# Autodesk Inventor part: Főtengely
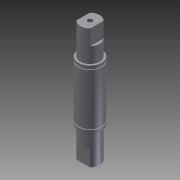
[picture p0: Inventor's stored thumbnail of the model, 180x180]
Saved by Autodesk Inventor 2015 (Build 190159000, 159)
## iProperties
Created: 2013-02
Part Number: Főtengely
Material: Generic
Document SubType Name: Modeling
Designer: Marci
Density: 1 g/cm^3
Appearance: Default
Author: Marci
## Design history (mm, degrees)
sketch "Sketch1"
  geometry: C1 r 15 at (0, 0); 1 further point
  constraints: 1 centre point, 1 coincident
  dimensions: "d0" = 30 diameter of C1
extrude "Extrusion1" new body sketch "Sketch1" distance "d1" = 76; taper "d2" = 0 deg
sketch "Sketch2"
  geometry: C1 r 15 at (0, 0) reference; C2 r 12.5 at (0, 0)
  constraints: 1 centre point, 1 coincident
  dimensions: "d3" = 25 diameter of C2
extrude "Extrusion2" join sketch "Sketch2" distance "d4" = 34; taper "d5" = 0 deg
sketch "Sketch3"
  geometry: C1 r 15 at (0, 0) reference; C2 r 12.5 at (0, 0)
  constraints: 1 centre point, 1 coincident
  dimensions: "d6" = 25 diameter of C2
extrude "Extrusion3" join sketch "Sketch3" distance "d7" = 34; taper "d8" = 0 deg
sketch "Sketch4"
  geometry: L1 (15, 5)-(14, 5); L2 (14, 5)-(14, 3.7); L3 (14, 3.7)-(17.377, 3.7); L4 (17.377, 3.7)-(17.377, 5); L5 (17.377, 5)-(15, 5); L6 (15, 71)-(14, 71); L7 (14, 71)-(14, 72.3); L8 (14, 72.3)-(17.377, 72.3); L9 (17.377, 72.3)-(17.377, 71); L10 (17.377, 71)-(15, 71); L11 (0, -62.8)-(0, 138.8) reference; 1 further point
  constraints: 20 end point
  dimensions: "d12" = 1 distance of L1.start L1.end; "d13" = 1.3 distance of L1.end L2.end
revolve "Revolution1" sketch "Sketch4" stored, may be unused: angle "d14" = 90 deg
sketch "Sketch5"
  geometry: L1 (0, 9)-(-8.675, 9); L2 (0, 9)-(14.413, 9); L3 (14.413, 9)-(14.413, 17.12); L4 (14.413, 17.12)-(-16.16, 17.12); L5 (-16.16, 17.12)-(-16.16, 9); L6 (-16.16, 9)-(-8.675, 9); L7 (0, -9)-(-8.675, -9); L8 (0, -9)-(14.413, -9); L9 (14.413, -9)-(14.413, -17.12); L10 (14.413, -17.12)-(-16.16, -17.12); L11 (-16.16, -17.12)-(-16.16, -9); L12 (-16.16, -9)-(-8.675, -9); 1 further point
  constraints: 24 end point, 2 parallel, 1 collinear, 1 perpendicular, 2 other
  dimensions: "d15" = 9 distance of point (0, 0) L1.start
extrude "Extrusion4" cut sketch "Sketch5" distance "d16" = 14; taper "d17" = 0 deg
sketch "Sketch6"
  geometry: L1 (9, 0)-(9, -15.159); L2 (9, -15.159)-(18.092, -15.159); L3 (18.092, -15.159)-(18.092, 20.124); L4 (18.092, 20.124)-(9, 20.124); L5 (9, 20.124)-(9, 0); L6 (-9, 0)-(-9, -15.159); L7 (-9, -15.159)-(-18.092, -15.159); L8 (-18.092, -15.159)-(-18.092, 20.124); L9 (-18.092, 20.124)-(-9, 20.124); L10 (-9, 20.124)-(-9, 0)
  constraints: 20 end point, 1 collinear, 1 parallel
extrude "Extrusion5" cut sketch "Sketch6" distance "d19" = 14; taper "d20" = 0 deg
sketch "Sketch11"
  geometry: L1 (9, -8.675)-(9, 8.675) reference; L2 (-9, 8.675)-(-9, -8.675) reference; A1 r 12.5 centre (0, 0) between (9, 8.675) and (-9, 8.675) reference; A2 r 12.5 centre (0, 0) between (-9, -8.675) and (9, -8.675) reference
extrude "Extrusion10" join sketch "Sketch11" distance "d41" = 6; taper "d42" = 0 deg
sketch "Sketch12"
  geometry: L1 (8.675, 9)-(-8.675, 9) reference; L2 (-8.675, -9)-(8.675, -9) reference; A1 r 12.5 centre (0, 0) between (-8.675, 9) and (-8.675, -9) reference; A2 r 12.5 centre (0, 0) between (8.675, -9) and (8.675, 9) reference
extrude "Extrusion11" join sketch "Sketch12" distance "d43" = 6; taper "d44" = 0 deg
sketch "Sketch13"
  geometry: C1 r 2.9 at (0, 0); A1 r 12.5 centre (0, 0) between (9, 8.675) and (-9, 8.675) reference
  constraints: 1 centre point, 1 coincident
  dimensions: "d45" = 5.8 diameter of C1
extrude "Extrusion12" cut sketch "Sketch13" distance "d46" = 20; taper "d47" = 0 deg
sketch "Sketch14"
  geometry: C1 r 2.9 at (0, 0); A1 r 12.5 centre (0, 0) between (-8.675, 9) and (-8.675, -9) reference
  constraints: 1 centre point, 1 coincident
  dimensions: "d48" = 5.8 diameter of C1
extrude "Extrusion13" cut sketch "Sketch14" distance "d49" = 20; taper "d50" = 0 deg
thread "Thread3" dims "d51" = 10, "d52" = 0
thread "Thread4" dims "d53" = 10, "d54" = 0
body "Solid1"
